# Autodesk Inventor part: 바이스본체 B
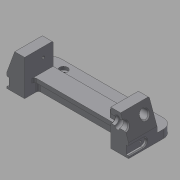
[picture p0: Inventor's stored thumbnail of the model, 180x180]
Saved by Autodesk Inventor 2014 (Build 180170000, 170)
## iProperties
Created: 2017-04
Part Number: 바이스본체 B
Material: 일반
Document SubType Name: Modeling
Designer: mduedu
Density: 1 g/cm^3
Appearance: 기본값
Author: mduedu
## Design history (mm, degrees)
sketch "스케치1"
  geometry: L1 (-75, 0)-(75, 0); L2 (-75, 0)-(-75, 17); L3 (-53, 17)-(53, 17); L4 (75, 17)-(75, 0); L5 (-75, 17)-(-65.173, 44); L6 (-65.173, 44)-(-53, 44); L7 (-53, 44)-(-53, 17); L8 (0, 0)-(0, 17); L9 (75, 17)-(65.173, 44); L10 (65.173, 44)-(53, 44); L11 (53, 44)-(53, 17); 1 further point
  constraints: 22 end point, 4 perpendicular, 2 horizontal alignment, 2 midpoint, 2 symmetric about line, 1 coincident, 1 collinear, 1 horizontal, 1 vertical
  dimensions: "d0" = 150 distance of L1.start L1.end; "d1" = 17 distance of L1.start L2.end; "d2" = 27 distance of L3.start L6.end; "d3" = 22 distance of L3.start L2.end; "d4" = 70 deg angle of L3 L5; "d54" = 20 deg angle of L9 L4
extrude "돌출1" new body sketch "스케치1" stored distance "d5" = 70; taper "d6" = 0 deg
sketch "스케치2"
  geometry: L1 (0, 70)-(106, 70) reference; L2 (106, 70)-(106, 0) reference; L3 (106, 0)-(0, 0) reference; L4 (0, 47)-(106, 47); L5 (106, 47)-(106, 23); L6 (106, 23)-(0, 23); L7 (0, 23)-(0, 47); L8 (0, 70)-(0, 0) reference; 2 further points
  constraints: 8 end point, 2 parallel, 2 point on line, 1 horizontal, 1 horizontal alignment, 1 midpoint, 1 perpendicular
  dimensions: "d7" = 24 distance between parallel lines of L6 L4
extrude "돌출2" cut sketch "스케치2" stored distance "d9" = 70; taper "d10" = 0 deg
sketch "스케치3"
  geometry: L1 (22, -23)-(128, -23) reference; L2 (128, -47)-(22, -47) reference; L3 (22, -18)-(128, -18); L4 (128, -52)-(22, -52); L5 (22, -18)-(22, -52); L6 (128, -18)-(128, -52); 1 further point
  constraints: 8 end point, 3 parallel, 2 point on line, 1 perpendicular
  dimensions: "d11" = 5 distance between parallel lines of L3 L1; "d12" = 5 distance between parallel lines of L4 L2
extrude "돌출3" cut sketch "스케치3" distance "d13" = 12; taper "d14" = 0 deg
fillet "모깎기1" dims "d15" = 3, "d16" = 3
sketch "스케치4"
  geometry: L1 (103, 23)-(3, 23) reference; L2 (0, 26)-(0, 0) reference; L3 (106, 0)-(0, 0) reference; L4 (106, 26)-(106, 0) reference; L5 (96, 0)-(90, 0); L6 (90, 0)-(90, 19.5); L7 (96, 19.5)-(96, 0); L8 (90, 19.5)-(96, 19.5); A1 r 3 centre (3, 26) between (0, 26) and (3, 23) reference; A2 r 3 centre (103, 26) between (103, 23) and (106, 26) reference; 1 further point
  constraints: 8 end point, 2 perpendicular, 1 horizontal, 1 parallel, 1 point on line
  dimensions: "d17" = 10 distance between parallel lines of L7 L4; "d18" = 6 distance between parallel lines of L7 L6; "d27" = 3.5 distance between parallel lines of L8 L1
extrude "돌출4" join sketch "스케치4" distance "d19" = 12; taper "d20" = 0 deg
chamfer "모따기1" distance "d21" = 3; stored, may be unused: second distance "d22" = 2, angle "d23" = 45 deg
chamfer "모따기2" distance "d24" = 3; stored, may be unused: second distance "d25" = 2, angle "d26" = 45 deg
sketch "스케치5"
  geometry: L1 (-15.5, 35.8)-(-15.5, -25.8) reference; L2 (19.5, 0)-(0, 0) reference; C1 r 6.5 at (9.5, 15); 1 further point
  constraints: 1 centre point
  dimensions: "d28" = 13 diameter of C1; "d30" = 15 distance from line of C1.centre L2; "d31" = 25 distance from line of C1.centre L1
extrude "돌출5" cut sketch "스케치5" stored distance "d32" = 12; taper "d33" = 0 deg
sketch "스케치6"
  geometry: C1 r 5 at (-10, 15); C2 r 5 at (-60, 15); A1 r 6.5 centre (-10, 15) between (-15.766, 12) and (-4.234, 12) reference; A2 r 6.5 centre (-60, 15) between (-65.766, 12) and (-54.234, 12) reference; 1 further point
  constraints: 2 centre point, 2 coincident
  dimensions: "d34" = 10 diameter of C1; "d35" = 10 diameter of C2 (= d34)
extrude "돌출6" cut sketch "스케치6" stored distance "d36" = 12; taper "d37" = 0 deg
chamfer "모따기3" distance "d38" = 1; stored, may be unused: second distance "d39" = 2, angle "d40" = 45 deg
chamfer "모따기4" distance "d41" = 1; stored, may be unused: second distance "d42" = 2, angle "d43" = 45 deg
sketch "스케치7"
  geometry: L1 (-35, 35.8)-(-35, -25.8) reference; L2 (-70, 0)-(0, 0) reference; C1 r 5 at (-35, 15); 1 further point
  constraints: 1 centre point, 1 point on line
  dimensions: "d44" = 10 diameter of C1; "d45" = 15 distance from line of C1.centre L2
extrude "돌출7" cut sketch "스케치7" stored distance "d46" = 12; taper "d47" = 0 deg
chamfer "모따기5" distance "d48" = 1; stored, may be unused: second distance "d49" = 2, angle "d50" = 45 deg
node "작업축1"
sketch "스케치8"
  geometry: L1 (-105, 32)-(105, 32) reference; L2 (58, 32)-(64, 32); L3 (64, 32)-(64, 40); L4 (64, 40)-(58, 40); L5 (58, 40)-(58, 32); L6 (53, 38)-(53, 26) reference; 1 further point
  constraints: 8 end point, 2 parallel, 1 horizontal, 1 perpendicular, 1 point on line
  dimensions: "d51" = 5 distance from line of L6 L2.start; "d52" = 6 distance of L3.end L4.end; "d53" = 16 diameter of L4 L1
revolve "회전1" sketch "스케치8" stored, may be unused: angle "d55" = 90 deg
fillet "모깎기2"
chamfer "모따기6" distance "d56" = 1; stored, may be unused: second distance "d57" = 2, angle "d58" = 45 deg
sketch "스케치9"
  geometry: L1 (17.5, 3)-(52.5, 3); L2 (52.5, 13)-(17.5, 13); L3 (70, 0)-(0, 0) reference; L4 (17.5, 8)-(52.5, 8); A1 r 5 centre (17.5, 8) between (17.5, 13) and (17.5, 3); A2 r 5 centre (52.5, 8) between (52.5, 3) and (52.5, 13); 3 further points
  constraints: 6 end point, 4 point on circle, 3 tangent, 2 centre point, 2 midpoint, 2 parallel, 1 horizontal, 1 vertical alignment
  dimensions: "d59" = 35 distance of L4.start L4.end; "d61" = 5 radius of A2; "d62" = 8 distance between parallel lines of L3 L4
extrude "돌출8" cut sketch "스케치9" distance "d63" = 3; taper "d64" = 0 deg
chamfer "모따기7" distance "d65" = 1; stored, may be unused: second distance "d66" = 2, angle "d67" = 45 deg
chamfer "모따기8" distance "d68" = 1; stored, may be unused: second distance "d69" = 2, angle "d70" = 45 deg
feature "분할1"
sketch "스케치10"
  geometry: A1 r 5 centre (0, 0) between (0, 5) and (0, -5) reference; 1 further point
  constraints: 1 coincident
hole "구멍1" sketch "스케치10" at (0, 0) diameter "d71" = 2.459; stored, may be unused: countersink angle "d75" = 90 deg, drill point angle "d77" = 120 deg; dims "d72" = 4.5, "d73" = 4, "d74" = 2, "d76" = 6
sketch "스케치11"
  geometry: L1 (0, 0)-(0, 27) reference; L2 (0, 27)-(-35, 27) reference; 2 further points
  dimensions: "d78" = 12 distance from line of point (-12, 15.5) L1; "d79" = 11.5 distance from line of point (-12, 15.5) L2
hole "구멍2" sketch "스케치11" at (-12, 15.5) diameter "d80" = 3.242; stored, may be unused: countersink angle "d84" = 90 deg, drill point angle "d86" = 120 deg; dims "d81" = 6, "d82" = 4, "d83" = 2, "d85" = 8
sketch "스케치12"
  geometry: L1 (-75, -35)-(-75, 0) reference; L2 (75, -35)-(75, 0) reference; L3 (75, -35)-(-75, -35); L4 (-75, -35)-(-75, -55); L5 (-75, -55)-(75, -55); L6 (75, -55)-(75, -35); 1 further point
  constraints: 8 end point, 2 parallel, 1 horizontal, 1 perpendicular, 1 point on line
  dimensions: "d87" = 20 distance of L3.end L4.end; "d89" = 150 distance of L4.end L5.end (derived)
extrude "돌출9" join sketch "스케치12" distance "d90" = 10; taper "d91" = 0 deg
sketch "스케치13"
  geometry: L1 (-75, 55)-(-75, 35) reference; L2 (75, 35)-(75, 55) reference; L3 (-75, 45)-(75, 45); 3 further points
  constraints: 2 end point, 2 midpoint, 2 point on line
  dimensions: "d92" = 50 horizontal distance of point (-50, 45) point (0, 0); "d93" = 100 distance of point (50, 45) point (-50, 45)
fillet "모깎기3" dims "d94" = 12
chamfer "모따기9" distance "d95" = 1; stored, may be unused: second distance "d96" = 2, angle "d97" = 45 deg
hole "구멍3" sketch "스케치13" diameter "d98" = 4.134; stored, may be unused: countersink angle "d102" = 90 deg, drill point angle "d104" = 118 deg; dims "d99" = 6, "d100" = 10, "d101" = 4, "d103" = 8
node "솔리드1"
mirror "대칭1"
mirror "대칭2"
mirror "대칭3"
mirror "대칭4"
node "투영된 루프1"
